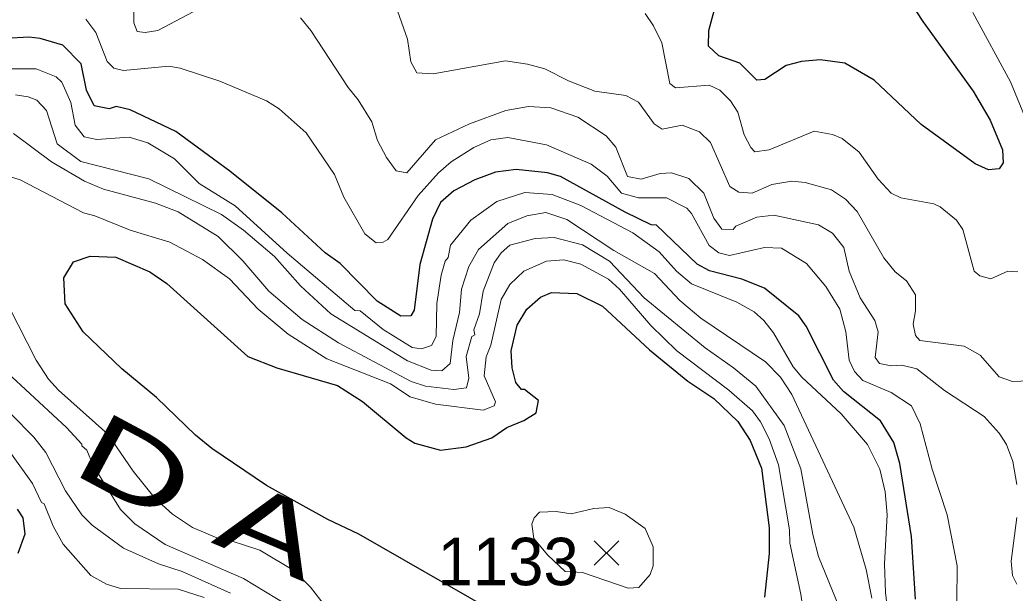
# Model space of a CAD drawing. Extents: x 265.7 to 292.1, y 7676.2 to 7704.2.
# Drawn here: x 275.523 to 277.2, y 7679.418 to 7680.384 of the extents above; entities that cross this region are included whole.
import ezdxf
from ezdxf.enums import TextEntityAlignment as Align

# ---------------------------------------------------------------- set-up
doc = ezdxf.new("R2010")
doc.units = 0
doc.header["$LTSCALE"] = 0.032
for name, color, linetype, lineweight in [('1', 7, 'Continuous', 25), ('2', 7, 'Continuous', 13), ('21', 7, 'Continuous', 25)]:
    doc.layers.add(name, color=color, linetype=linetype, lineweight=lineweight)
doc.layers.add('61', color=7, linetype='Continuous')

msp = doc.modelspace()

# ---------------------------------------------------------------- linework, layer by layer
at = {"layer": '1'}
for points in [[(276.9518, 7680.5236), (277.0451, 7680.3807), (277.1297, 7680.2634), (277.1584, 7680.2148), (277.1792, 7680.1645), (277.18, 7680.1429), (277.1736, 7680.1326), (277.1553, 7680.131), (277.1329, 7680.1413), (277.0419, 7680.2076), (276.963, 7680.2818), (276.9135, 7680.3105), (276.872, 7680.3161), (276.8401, 7680.3137), (276.8145, 7680.3065), (276.7786, 7680.2834), (276.7651, 7680.2818), (276.7363, 7680.3105), (276.7012, 7680.3233), (276.6837, 7680.3392), (276.6844, 7680.3656), (276.6972, 7680.4135)], [(277.0324, 7679.408), (277.026, 7679.5134), (277.006, 7679.6362), (276.9957, 7679.6714), (276.9733, 7679.7081), (276.9111, 7679.7575), (276.8943, 7679.7767), (276.848, 7679.8677), (276.8361, 7679.8852), (276.7778, 7679.9315), (276.7395, 7679.9466), (276.6853, 7679.961), (276.6645, 7679.9722), (276.5959, 7680.0376), (276.5871, 7680.0384), (276.5432, 7680.0599), (276.4339, 7680.1198), (276.4124, 7680.1262), (276.3597, 7680.1318), (276.3246, 7680.127), (276.2895, 7680.1142), (276.2544, 7680.0959), (276.232, 7680.0759), (276.2184, 7680.048), (276.1969, 7679.9714), (276.1873, 7679.8948), (276.1817, 7679.8852), (276.165, 7679.8844), (276.1251, 7679.9099), (276.0628, 7679.973), (276.0373, 7679.9913), (275.9647, 7680.0584), (275.8769, 7680.1286), (275.786, 7680.1956), (275.7086, 7680.2323), (275.6854, 7680.2379), (275.6734, 7680.2339), (275.6479, 7680.2387), (275.6351, 7680.265), (275.6263, 7680.3097), (275.5952, 7680.3408), (275.5569, 7680.352), (275.5378, 7680.3544), (275.4995, 7680.352)], [(276.3195, 7679.3882), (276.094, 7679.5173), (276.0421, 7679.5421), (275.9384, 7679.5995), (275.8466, 7679.6618), (275.8187, 7679.6841), (275.7532, 7679.7472), (275.695, 7679.7958), (275.6296, 7679.8581), (275.5992, 7679.9052), (275.5968, 7679.949), (275.6136, 7679.9762), (275.6415, 7679.9857), (275.6846, 7679.9841), (275.7421, 7679.9594), (275.7708, 7679.9395), (275.9072, 7679.8166), (275.9559, 7679.7974), (276.0581, 7679.7679), (276.1004, 7679.7408), (276.1738, 7679.6793), (276.1889, 7679.6705), (276.232, 7679.6586), (276.2751, 7679.6642), (276.3182, 7679.6793), (276.3437, 7679.6969), (276.3725, 7679.7088), (276.3932, 7679.7216), (276.3972, 7679.7424), (276.3733, 7679.7607), (276.3685, 7679.7607), (276.3589, 7679.7727), (276.3525, 7679.7974), (276.3509, 7679.8262), (276.3613, 7679.8693), (276.3772, 7679.8964), (276.4004, 7679.9163), (276.4187, 7679.9243), (276.4618, 7679.9227), (276.5049, 7679.9012), (276.5839, 7679.8278), (276.6486, 7679.7751), (276.6924, 7679.7456), (276.7331, 7679.7073), (276.7539, 7679.6753), (276.773, 7679.6283), (276.7858, 7679.5277), (276.7858, 7679.4846), (276.7778, 7679.4112)], [(275.5186, 7679.5596), (275.5282, 7679.5445), (275.5314, 7679.5174), (275.5194, 7679.4846)]]:
    msp.add_lwpolyline(points, dxfattribs=at)
at = {"layer": '2'}
for points in [[(275.7149, 7680.4238), (275.7149, 7680.3784), (275.7205, 7680.364), (275.7341, 7680.3624), (275.7556, 7680.3656), (275.8554, 7680.419)], [(277.1018, 7679.3426), (277.1026, 7679.4639), (277.0858, 7679.5501), (277.0603, 7679.6267), (277.0403, 7679.7033), (277.026, 7679.7336), (276.9917, 7679.7559), (276.9438, 7679.7759), (276.9294, 7679.7911), (276.9207, 7679.8102), (276.9151, 7679.8581), (276.9047, 7679.8964), (276.8816, 7679.9347), (276.8488, 7679.973), (276.8066, 7679.9993), (276.7778, 7680.0001), (276.7188, 7679.9865), (276.7012, 7679.9913), (276.6845, 7680.0033), (276.6549, 7680.0576), (276.647, 7680.0663), (276.6126, 7680.0839), (276.5656, 7680.0839), (276.5368, 7680.0919), (276.5129, 7680.1206), (276.4858, 7680.1406), (276.4108, 7680.1733), (276.3453, 7680.1852), (276.3166, 7680.1813), (276.2879, 7680.1685), (276.2496, 7680.1445), (276.2288, 7680.1262), (276.1945, 7680.0879), (276.1434, 7680.0137), (276.1355, 7680.0089), (276.1235, 7680.0081), (276.1043, 7680.0233), (276.0692, 7680.0847), (276.0533, 7680.123), (276.0054, 7680.1932), (275.9599, 7680.2339), (275.9384, 7680.2475), (275.8602, 7680.2802), (275.7931, 7680.3025), (275.774, 7680.3057), (275.6974, 7680.2985), (275.6814, 7680.3025), (275.6703, 7680.3137), (275.6511, 7680.3624), (275.6343, 7680.3847)], [(275.9958, 7680.3871), (276.0134, 7680.3656), (276.0764, 7680.2698), (276.0932, 7680.2491), (276.1163, 7680.2116), (276.1259, 7680.1805), (276.141, 7680.1517), (276.157, 7680.1294), (276.1754, 7680.1262), (276.2232, 7680.1813), (276.2807, 7680.2084), (276.3421, 7680.2307), (276.3804, 7680.2379), (276.4179, 7680.2355), (276.4634, 7680.2196), (276.5113, 7680.1884), (276.5273, 7680.1693), (276.5472, 7680.1198), (276.5703, 7680.115), (276.6023, 7680.1246), (276.6214, 7680.1262), (276.6502, 7680.1166), (276.6757, 7680.0919), (276.6924, 7680.0496), (276.706, 7680.0312), (276.7252, 7680.0304), (276.7299, 7680.036), (276.7651, 7680.0512), (276.7938, 7680.0544), (276.8688, 7680.0384), (276.8927, 7680.0241), (276.9119, 7680.0001), (276.9207, 7679.9602), (276.939, 7679.9155), (276.9637, 7679.8772), (276.9693, 7679.8581), (276.9645, 7679.815), (276.9717, 7679.8046), (276.9917, 7679.8006), (277.0092, 7679.8022), (277.0348, 7679.7958), (277.0811, 7679.7591), (277.1481, 7679.7152), (277.1736, 7679.6873), (277.1856, 7679.6682), (277.1967, 7679.6394), (277.2031, 7679.6011)], [(276.4922, 7680.2634), (276.4475, 7680.281), (276.4076, 7680.3009), (276.3788, 7680.3089), (276.3413, 7680.3145), (276.2193, 7680.293), (276.1921, 7680.2946), (276.1817, 7680.3129), (276.1762, 7680.3512), (276.1594, 7680.3991)], [(277.2047, 7679.9594), (277.188, 7679.9602), (277.1593, 7679.9474), (277.1409, 7679.9522), (277.1313, 7679.9602), (277.1122, 7680.0304), (277.1018, 7680.0464), (277.0739, 7680.0687), (277.0635, 7680.0735), (277.0076, 7680.0839), (276.9917, 7680.0919), (276.9693, 7680.115), (276.9374, 7680.1605), (276.9087, 7680.1836), (276.8927, 7680.1908), (276.8616, 7680.1964), (276.7858, 7680.1645), (276.7619, 7680.1613), (276.7547, 7680.1685), (276.7435, 7680.19), (276.7331, 7680.2283), (276.7204, 7680.2475), (276.7028, 7680.265), (276.6845, 7680.2738), (276.6278, 7680.269), (276.6182, 7680.2762), (276.6047, 7680.3448), (276.5911, 7680.3736), (276.5767, 7680.3943)], [(277.1289, 7680.3959), (277.1928, 7680.2794), (277.2319, 7680.1837)], [(275.5027, 7680.3009), (275.5506, 7680.3009), (275.5841, 7680.2874), (275.5936, 7680.2786), (275.6088, 7680.2443), (275.616, 7680.206), (275.6311, 7680.1868), (275.6527, 7680.182), (275.707, 7680.186), (275.7389, 7680.1765), (275.7836, 7680.1493), (275.8251, 7680.1078), (275.8857, 7680.0703), (275.9735, 7679.9905), (276.0876, 7679.894), (276.0964, 7679.8932), (276.1355, 7679.8621), (276.1841, 7679.8317), (276.2001, 7679.8294), (276.2169, 7679.8349), (276.2248, 7679.8501), (276.2256, 7679.906), (276.2328, 7679.9538), (276.24, 7679.977), (276.2448, 7679.9834), (276.2488, 7680.0041), (276.2831, 7680.0464), (276.327, 7680.0775), (276.3741, 7680.0927), (276.4203, 7680.0895), (276.4682, 7680.0711), (276.556, 7680.0249), (276.6007, 7679.9929), (276.6294, 7679.9602), (276.6549, 7679.9387), (276.7315, 7679.9083), (276.7603, 7679.8916), (276.777, 7679.8772), (276.793, 7679.8565), (276.8265, 7679.799), (276.8409, 7679.7815), (276.9071, 7679.72), (276.9518, 7679.6682), (276.9725, 7679.6267), (276.9813, 7679.5884), (276.9845, 7679.5501), (276.9805, 7679.4671), (276.9821, 7679.4192), (276.9901, 7679.3474)], [(276.6709, 7679.8812), (276.635, 7679.9107), (276.5927, 7679.9562), (276.5241, 7679.9953), (276.4451, 7680.0472), (276.4092, 7680.0592), (276.3772, 7680.0536), (276.3453, 7680.0408), (276.2959, 7679.9969), (276.2799, 7679.9682), (276.2671, 7679.9299), (276.2639, 7679.8908), (276.2528, 7679.8437), (276.248, 7679.8046), (276.2344, 7679.7926), (276.2161, 7679.7934), (276.1762, 7679.8094), (276.0469, 7679.8884), (275.9958, 7679.9355), (275.9519, 7679.985), (275.9001, 7680.0296), (275.8626, 7680.056), (275.7405, 7680.1158), (275.6256, 7680.1453), (275.5857, 7680.1749), (275.5681, 7680.2307), (275.5514, 7680.2483), (275.537, 7680.2539), (275.5154, 7680.2571)], [(276.6685, 7680.1948), (276.639, 7680.206), (276.6055, 7680.1996), (276.5919, 7680.2084), (276.5656, 7680.2451), (276.544, 7680.2563), (276.4922, 7680.2634)], [(275.5122, 7680.1924), (275.5761, 7680.1445), (275.632, 7680.1118), (275.6639, 7680.0983), (275.7516, 7680.0751), (275.7899, 7680.06), (275.857, 7680.0185), (275.8985, 7679.9778), (275.9423, 7679.9267), (275.999, 7679.8788), (276.0597, 7679.8397), (276.1825, 7679.7743), (276.2065, 7679.7663), (276.2544, 7679.7607), (276.2759, 7679.7639), (276.2799, 7679.7799), (276.2751, 7679.8166), (276.2847, 7679.8501), (276.2895, 7679.8533), (276.2879, 7679.8613), (276.2974, 7679.8884), (276.3038, 7679.9267), (276.3222, 7679.9746), (276.3341, 7679.9913), (276.3485, 7680.0041), (276.3916, 7680.0153), (276.4235, 7680.0169), (276.4714, 7680.0049), (276.5169, 7679.977), (276.5751, 7679.9155), (276.6781, 7679.8309), (276.726, 7679.7974), (276.7635, 7679.7663), (276.8113, 7679.7001), (276.8393, 7679.6275), (276.8592, 7679.5166), (276.8688, 7679.4798), (276.9151, 7679.3665)], [(277.2374, 7679.7759), (277.196, 7679.7743), (277.1736, 7679.7823), (277.1417, 7679.819), (277.1146, 7679.8341), (277.0396, 7679.8437), (277.0324, 7679.8517), (277.0284, 7679.8708), (277.0324, 7679.8932), (277.0324, 7679.9203), (277.0172, 7679.9442), (276.9981, 7679.9594), (276.9789, 7679.9826), (276.9342, 7680.0608), (276.9143, 7680.0815), (276.8911, 7680.0975), (276.8464, 7680.1094), (276.8241, 7680.1118), (276.7906, 7680.1062), (276.7571, 7680.0919), (276.7347, 7680.0935), (276.7196, 7680.1031), (276.6868, 7680.1773), (276.6685, 7680.1948)], [(276.8201, 7679.5245), (276.8018, 7679.6338), (276.7858, 7679.6777), (276.7714, 7679.7065), (276.7579, 7679.7248), (276.718, 7679.7599), (276.6302, 7679.8262), (276.5863, 7679.8685), (276.5336, 7679.9299), (276.5153, 7679.9466), (276.4682, 7679.9722), (276.4395, 7679.9794), (276.4108, 7679.977), (276.3725, 7679.9602), (276.3485, 7679.9379), (276.3341, 7679.9123), (276.3166, 7679.8357), (276.3086, 7679.8158), (276.3054, 7679.7839), (276.3246, 7679.74), (276.3222, 7679.7336), (276.3038, 7679.7264), (276.2232, 7679.736), (276.1809, 7679.7488), (276.1474, 7679.7703), (276.0405, 7679.8126), (275.9751, 7679.8541), (275.9248, 7679.8964), (275.8761, 7679.9474), (275.8306, 7679.9802), (275.7756, 7680.0089), (275.7086, 7680.0296), (275.6495, 7680.0536), (275.6304, 7680.0584), (275.5234, 7680.1142), (275.4931, 7680.1238)], [(275.5051, 7679.8996), (275.5506, 7679.8102), (275.5713, 7679.7783), (275.5881, 7679.7599), (275.6711, 7679.6857), (275.7141, 7679.6235), (275.7508, 7679.5772), (275.7804, 7679.5509), (275.8139, 7679.5285), (275.8586, 7679.5094), (275.8793, 7679.5062), (275.9272, 7679.4902), (275.9847, 7679.4559), (276.0126, 7679.428), (276.0381, 7679.3953)], [(276.959, 7679.4096), (276.9494, 7679.4575), (276.9286, 7679.5293), (276.8241, 7679.7528), (276.8049, 7679.7815), (276.7794, 7679.8078), (276.6709, 7679.8812)], [(275.5641, 7679.5684), (275.5593, 7679.5708), (275.5442, 7679.6027), (275.5091, 7679.6522), (275.4333, 7679.7248), (275.395, 7679.7831), (275.3551, 7679.8365)], [(276.011, 7679.3753), (275.9001, 7679.4423), (275.7676, 7679.4998), (275.7165, 7679.5349), (275.6926, 7679.5588), (275.6463, 7679.6331), (275.6359, 7679.6586), (275.6272, 7679.6658), (275.6272, 7679.669), (275.6016, 7679.6969), (275.4859, 7679.8038)], [(275.5075, 7679.72), (275.5466, 7679.6809), (275.5665, 7679.6546), (275.6, 7679.59), (275.6272, 7679.5501), (275.6447, 7679.5325), (275.6974, 7679.4934), (275.7564, 7679.4671), (275.7963, 7679.4543), (275.8777, 7679.4176)], [(275.8338, 7679.4104), (275.7899, 7679.4248), (275.6926, 7679.4256), (275.6687, 7679.4328), (275.6423, 7679.4479), (275.596, 7679.5006), (275.5793, 7679.5309), (275.5641, 7679.5684)], [(277.2031, 7679.5453), (277.1936, 7679.4719), (277.196, 7679.4479), (277.2031, 7679.4328)], [(276.935, 7679.0984), (276.9055, 7679.1846), (276.8608, 7679.2995), (276.8488, 7679.3474), (276.8393, 7679.416), (276.8209, 7679.5022), (276.8201, 7679.5245)]]:
    msp.add_lwpolyline(points, dxfattribs=at)
msp.add_lwpolyline([(276.3891, 7679.5101), (276.4127, 7679.4817), (276.4419, 7679.4546), (276.471, 7679.4525), (276.548, 7679.4264), (276.5664, 7679.4272), (276.5855, 7679.4495), (276.5903, 7679.4639), (276.5903, 7679.4958), (276.5767, 7679.5269), (276.5432, 7679.5509), (276.5161, 7679.562), (276.4906, 7679.5604), (276.4523, 7679.5517), (276.4267, 7679.5556), (276.3988, 7679.5541), (276.39, 7679.5445), (276.386, 7679.5341)], close=True, dxfattribs=at)
at = {"layer": '21'}
for p, q in [((276.491, 7679.5063), (276.5322, 7679.4651)), ((276.5322, 7679.5063), (276.491, 7679.4651))]:
    msp.add_line(p, q, dxfattribs=at)

# ---------------------------------------------------------------- texts
at = {"layer": '61'}
for s, rotation, width, p in [('D', 331.845, 1.65, (275.6902, 7679.5774)), ('A', 337.061, 1.6, (275.9229, 7679.4702))]:
    msp.add_text(s, height=0.12, rotation=rotation, dxfattribs=dict(at, width=width)).set_placement(p, align=Align.CENTER)
msp.add_text('1133', height=0.08, dxfattribs=at).set_placement((276.3459, 7679.4312), align=Align.CENTER)

doc.saveas('drawing.dxf')
